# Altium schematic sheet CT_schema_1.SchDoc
size 678 x 615 mm
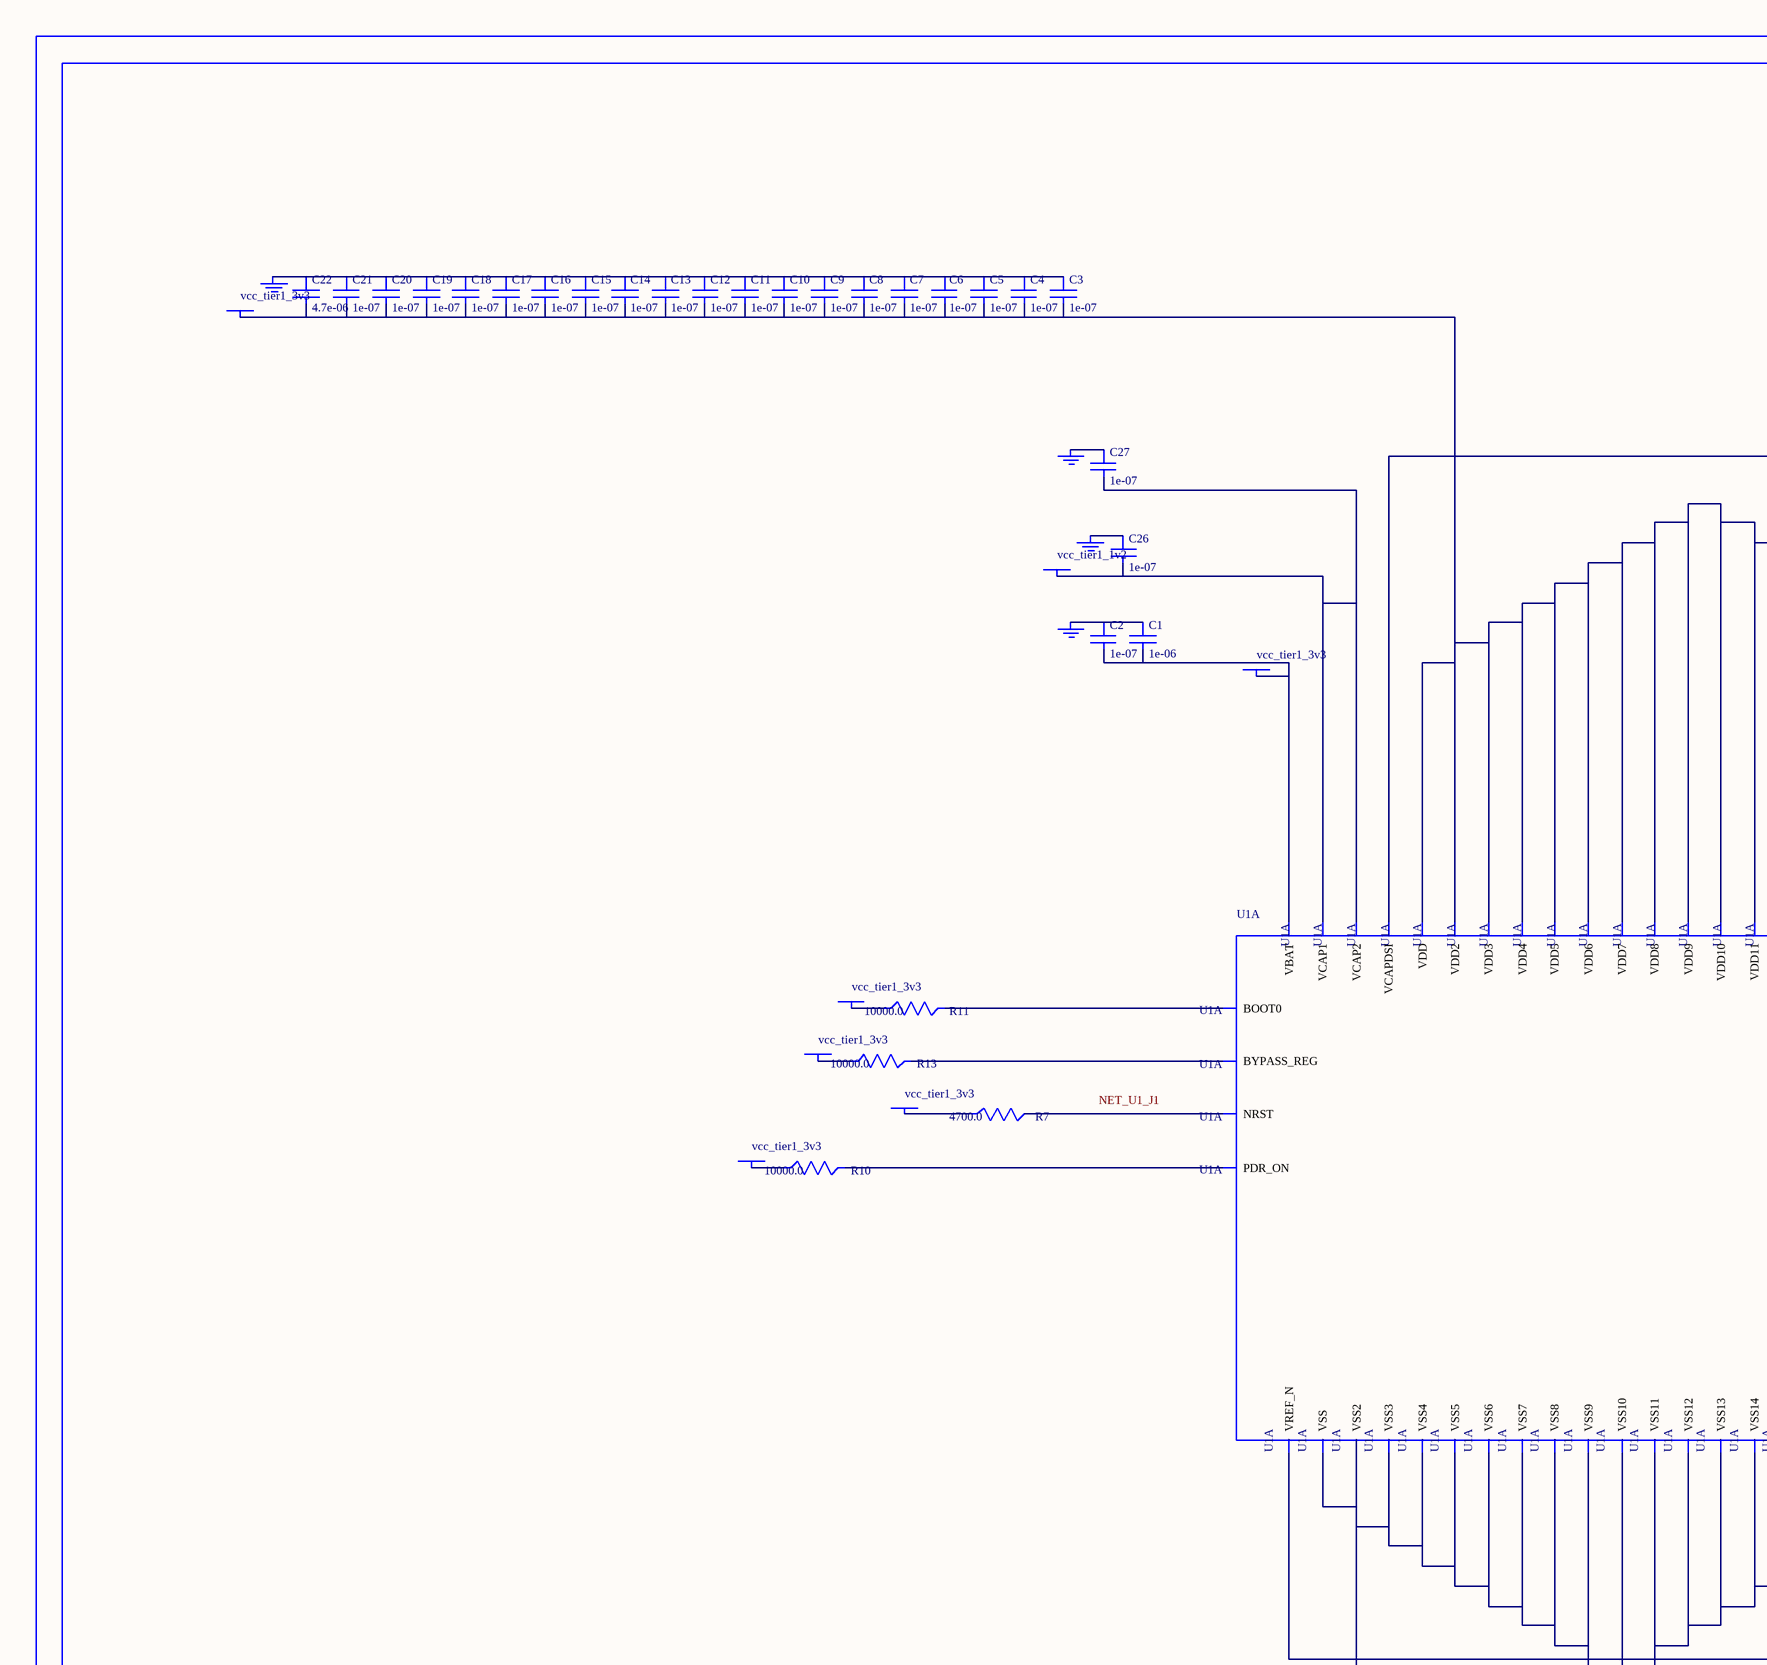
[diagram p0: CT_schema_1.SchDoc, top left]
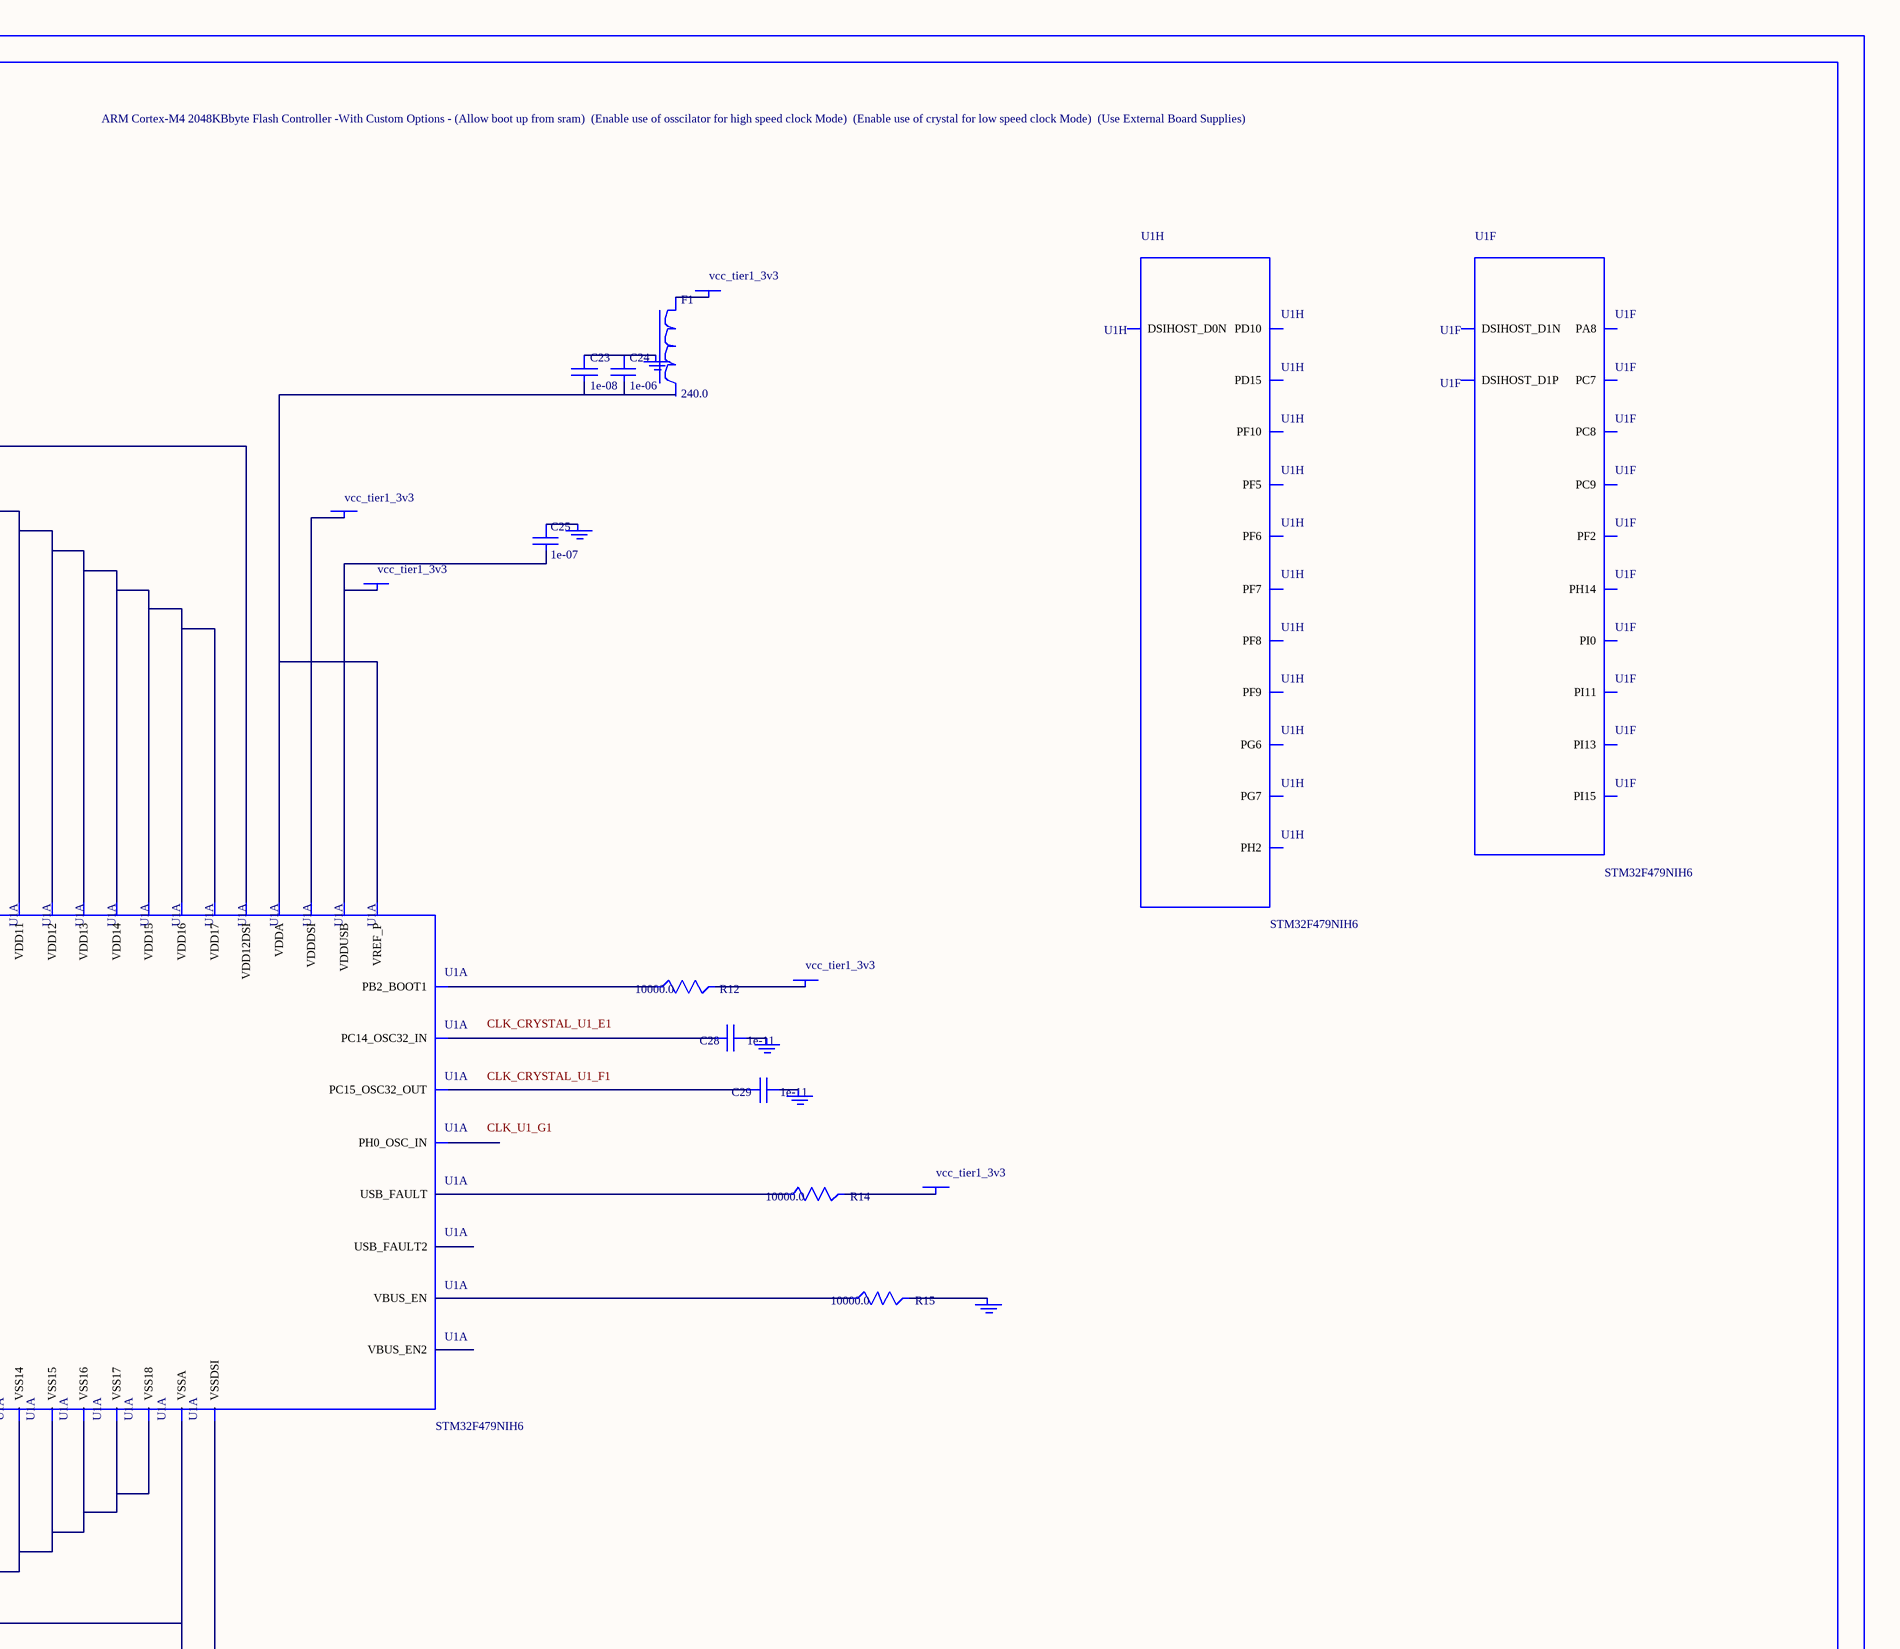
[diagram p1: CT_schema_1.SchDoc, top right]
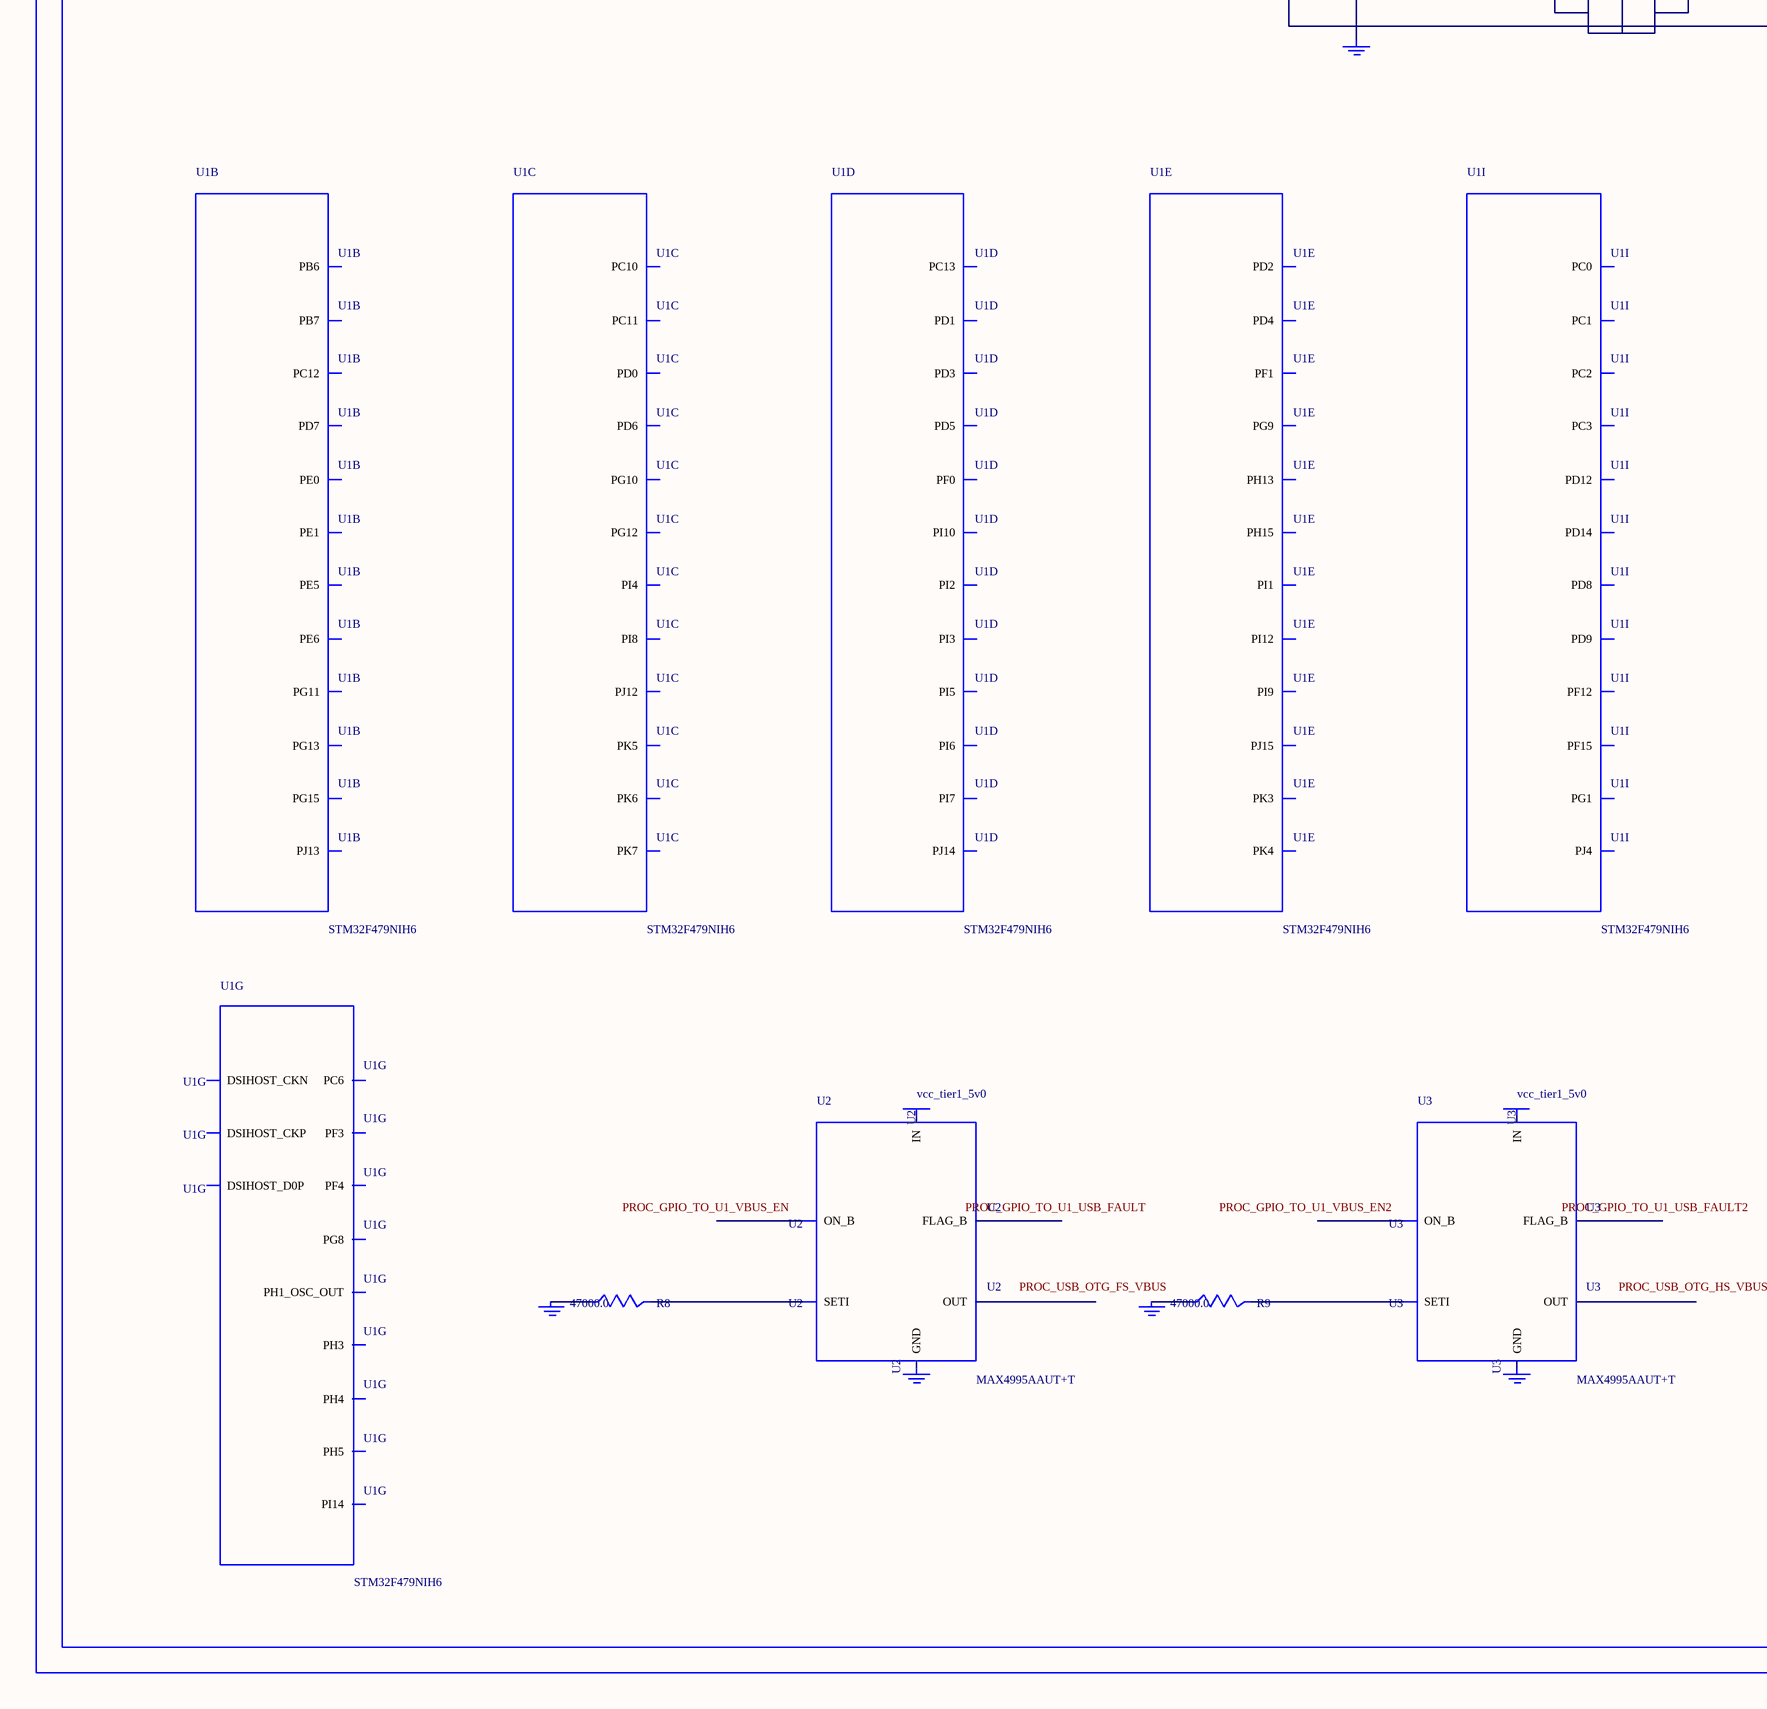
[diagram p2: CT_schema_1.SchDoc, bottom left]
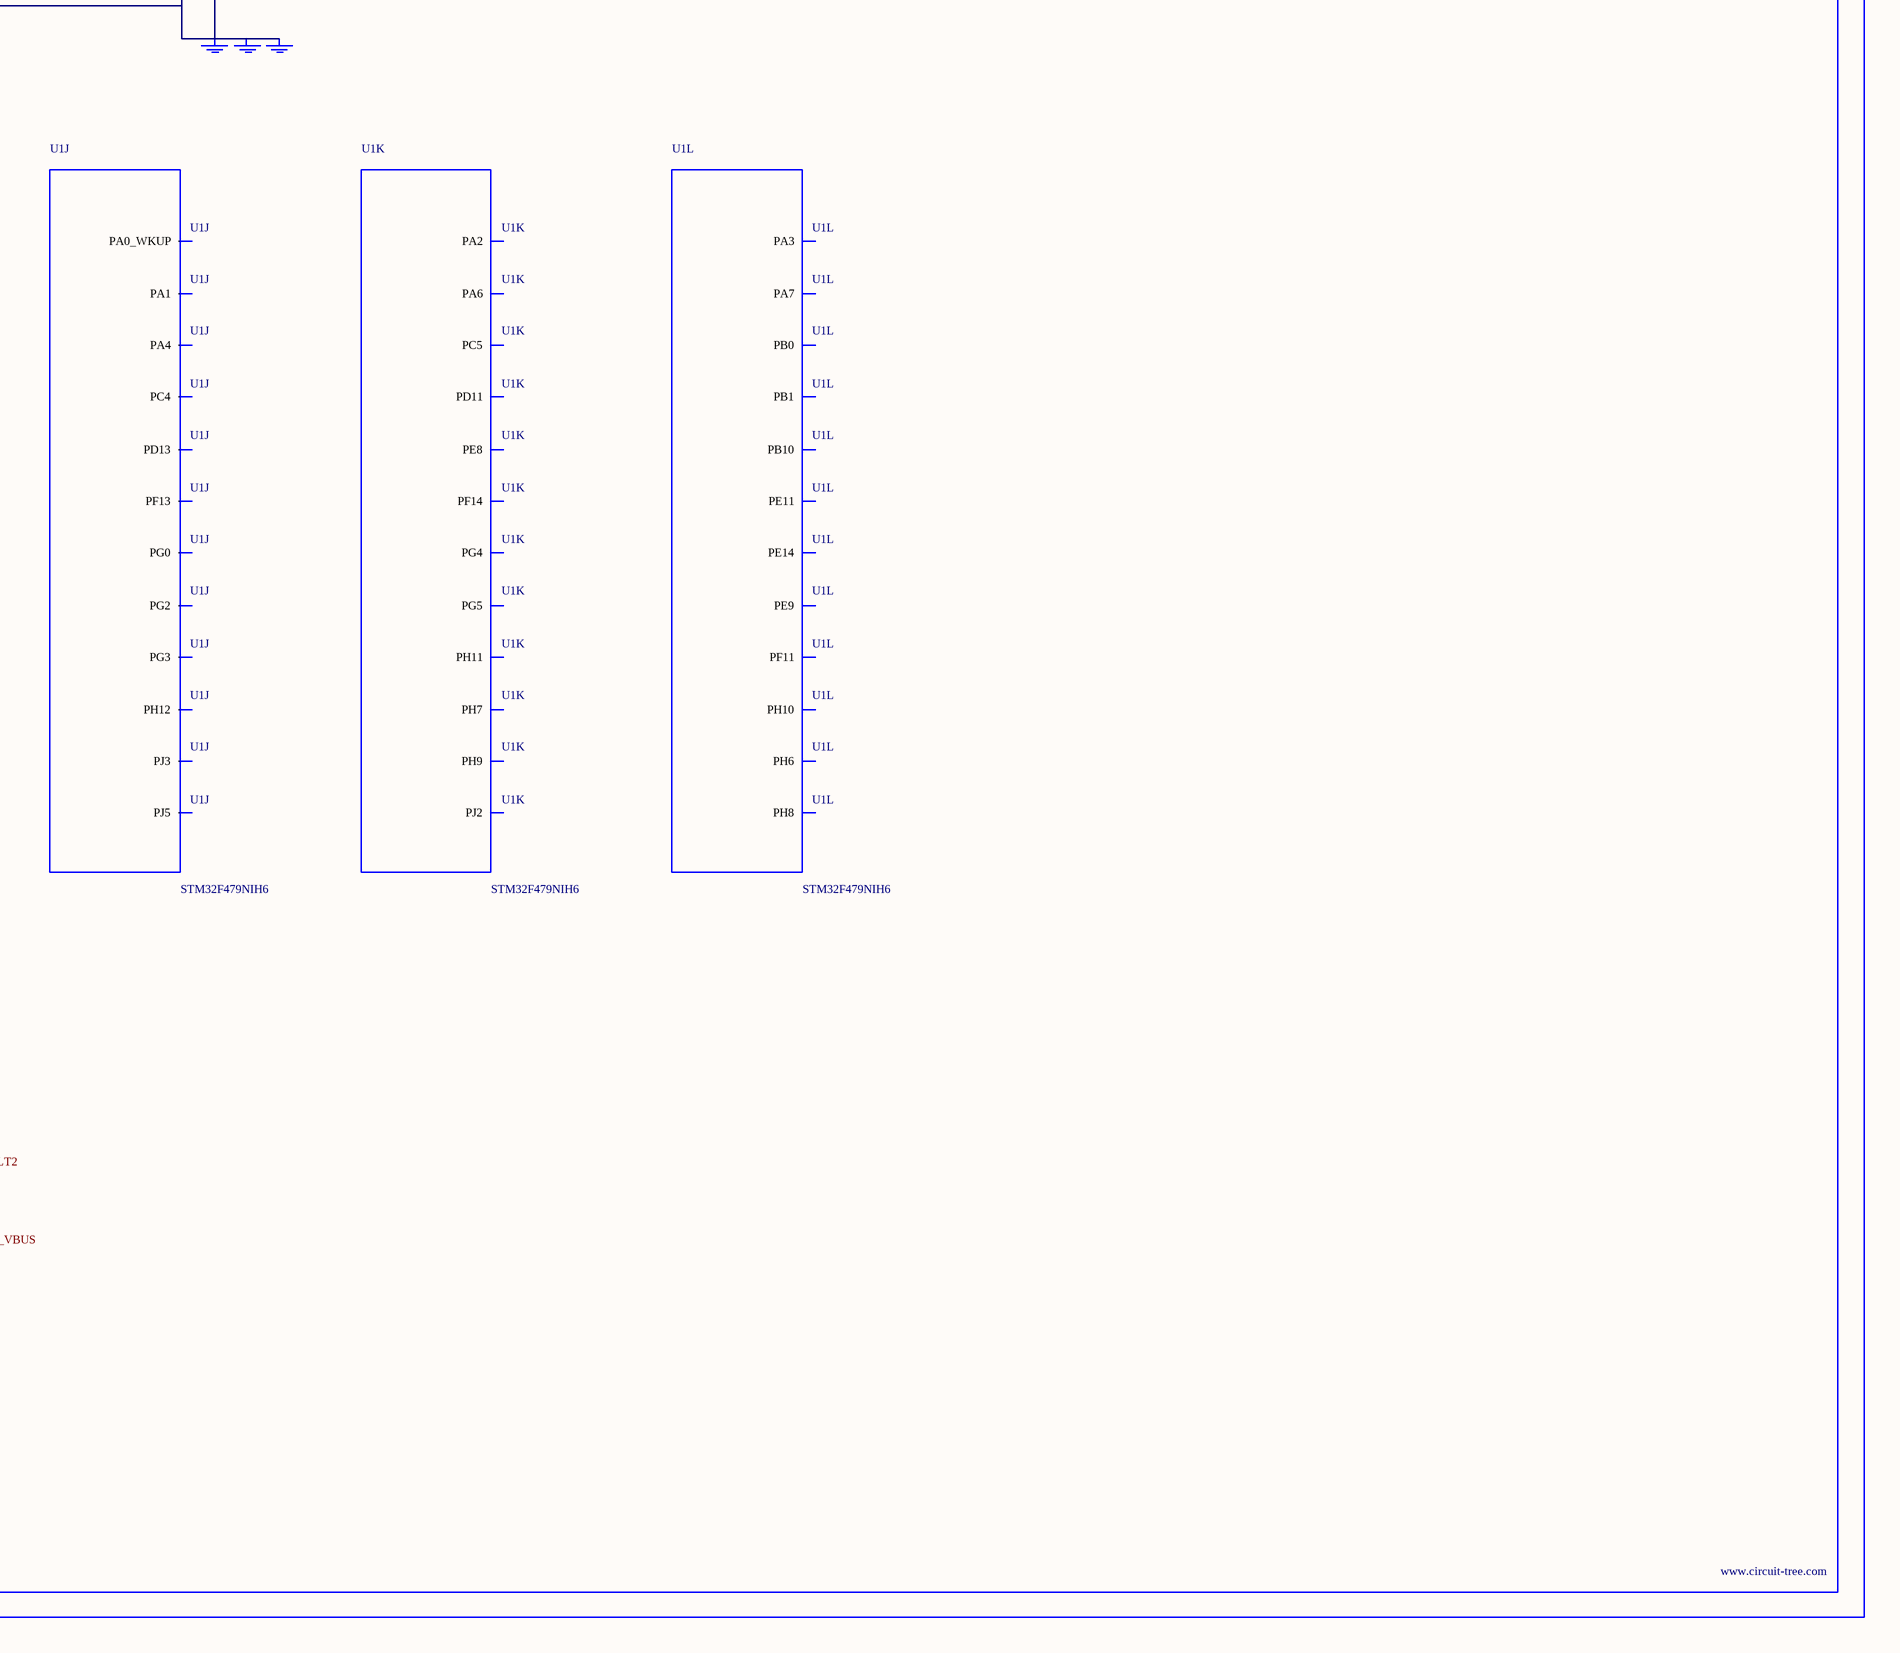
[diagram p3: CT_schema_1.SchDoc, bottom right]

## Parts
BORDER0  (no value)
C1  1e-06  [C0603]
C2  1e-07  [C0603]
C3  1e-07  [C0603]
C4  1e-07  [C0603]
C5  1e-07  [C0603]
C6  1e-07  [C0603]
C7  1e-07  [C0603]
C8  1e-07  [C0603]
C9  1e-07  [C0603]
C10  1e-07  [C0603]
C11  1e-07  [C0603]
C12  1e-07  [C0603]
C13  1e-07  [C0603]
C14  1e-07  [C0603]
C15  1e-07  [C0603]
C16  1e-07  [C0603]
C17  1e-07  [C0603]
C18  1e-07  [C0603]
C19  1e-07  [C0603]
C20  1e-07  [C0603]
C21  1e-07  [C0603]
C22  4.7e-06  [C0603]
C23  1e-08  [C0603]
C24  1e-06  [C0603]
C25  1e-07  [C0603]
C26  1e-07  [C0603]
C27  1e-07  [C0603]
C28  1e-11  [C0402]
C29  1e-11  [C0402]
F1  240.0  [L0603]
GND_INSTANCE_0_0  (no value)
GND_INSTANCE_0_1  (no value)
GND_INSTANCE_0_2  (no value)
GND_INSTANCE_0_3  (no value)
GND_INSTANCE_0_4  (no value)
GND_INSTANCE_0_5  (no value)
GND_INSTANCE_0_6  (no value)
GND_INSTANCE_0_7  (no value)
GND_INSTANCE_0_8  (no value)
GND_INSTANCE_0_9  (no value)
GND_INSTANCE_0_10  (no value)
GND_INSTANCE_0_11  (no value)
GND_INSTANCE_0_12  (no value)
GND_INSTANCE_0_13  (no value)
GND_INSTANCE_0_14  (no value)
GND_INSTANCE_0_15  (no value)
GND_INSTANCE_0_16  (no value)
POWER_INSTANCE_0_0  vcc_tier1_3v3
POWER_INSTANCE_0_1  vcc_tier1_3v3
POWER_INSTANCE_0_2  vcc_tier1_3v3
POWER_INSTANCE_0_3  vcc_tier1_3v3
POWER_INSTANCE_0_4  vcc_tier1_3v3
POWER_INSTANCE_0_5  vcc_tier1_3v3
POWER_INSTANCE_0_6  vcc_tier1_3v3
POWER_INSTANCE_0_7  vcc_tier1_3v3
POWER_INSTANCE_0_8  vcc_tier1_1v2
POWER_INSTANCE_0_9  vcc_tier1_3v3
POWER_INSTANCE_0_10  vcc_tier1_3v3
POWER_INSTANCE_0_11  vcc_tier1_3v3
POWER_INSTANCE_0_12  vcc_tier1_5v0
POWER_INSTANCE_0_13  vcc_tier1_5v0
R7  4700.0  [R0603]
R8  47000.0  [R0603]
R9  47000.0  [R0603]
R10  10000.0  [R0603]
R11  10000.0  [R0603]
R12  10000.0  [R0603]
R13  10000.0  [R0603]
R14  10000.0  [R0603]
R15  10000.0  [R0603]
U1  STM32F479NIH6  [TFBGA216]  (parts A,B,C,D,E,F,G,H,I,J,K,L of 17)
U2  MAX4995AAUT+T  [SOT-23-6]
U3  MAX4995AAUT+T  [SOT-23-6]

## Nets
NetC1_1: C1.1 C2.1 GND_INSTANCE_0_0.0(GND)
NetC1_2: C1.2 C2.2 POWER_INSTANCE_0_0.0(PWR) U1.C1(VBAT)
NetC3_1: C3.1 C4.1 C5.1 C6.1 C7.1 C8.1 C9.1 C10.1 C11.1 C12.1 C13.1 C14.1 C15.1 C16.1 C17.1 C18.1 C19.1 C20.1 C21.1 C22.1 GND_INSTANCE_0_2.0(GND)
NetC3_2: C3.2 C4.2 C5.2 C6.2 C7.2 C8.2 C9.2 C10.2 C11.2 C12.2 C13.2 C14.2 C15.2 C16.2 C17.2 C18.2 C19.2 C20.2 C21.2 C22.2 POWER_INSTANCE_0_2.0(PWR) U1.E7(VDD2) U1.E8(VDD3) U1.E9(VDD4) U1.E10(VDD) U1.F4(VDD6) U1.F5(VDD7) U1.F11(VDD5) U1.G5(VDD8) U1.H5(VDD9) U1.J5(VDD11) U1.J11(VDD10) U1.K5(VDD13) U1.K11(VDD12) U1.L7(VDD15) U1.L8(VDD16) U1.L9(VDD17) U1.L10(VDD14)
NetC23_1: C23.1 C24.1 GND_INSTANCE_0_1.0(GND)
NetC23_2: C23.2 C24.2 U1.P1(VREF_P) U1.R1(VDDA)
NetC25_1: C25.1 GND_INSTANCE_0_3.0(GND)
NetC25_2: C25.2 POWER_INSTANCE_0_4.0(PWR) U1.G11(VDDUSB)
NetC26_1: C26.1 GND_INSTANCE_0_4.0(GND)
NetC26_2: C26.2 C27.2 POWER_INSTANCE_0_8.0(PWR) U1.E11(VCAP2) U1.L11(VCAP1)
NetC27_1: C27.1 GND_INSTANCE_0_5.0(GND)
NetC28_1: C28.1 GND_INSTANCE_0_6.0(GND)
NetC28_2: C28.2 U1.E1(PC14_OSC32_IN)
NetC29_1: C29.1 GND_INSTANCE_0_7.0(GND)
NetC29_2: C29.2 U1.F1(PC15_OSC32_OUT)
NetF1_1: F1.1 POWER_INSTANCE_0_1.0(PWR)
NetGND_INSTANCE_0_8_0: GND_INSTANCE_0_8.0(GND) R15.2
NetGND_INSTANCE_0_9_0: GND_INSTANCE_0_9.0(GND) GND_INSTANCE_0_10.0(GND) GND_INSTANCE_0_11.0(GND) U1.G12(VSSDSI) U1.M1(VSSA) U1.N1(VREF_N)
NetGND_INSTANCE_0_12_0: GND_INSTANCE_0_12.0(GND) U1.F2(VSS2) U1.F6(VSS3) U1.F7(VSS4) U1.F8(VSS5) U1.F9(VSS6) U1.F10(VSS) U1.G6(VSS8) U1.G10(VSS7) U1.H6(VSS10) U1.H10(VSS9) U1.J6(VSS12) U1.J10(VSS11) U1.K6(VSS14) U1.K7(VSS15) U1.K8(VSS16) U1.K9(VSS17) U1.K10(VSS13) U1.L6(VSS18)
NetGND_INSTANCE_0_13_0: GND_INSTANCE_0_13.0(GND) R8.1
NetGND_INSTANCE_0_15_0: GND_INSTANCE_0_15.0(GND) R9.1
NetPOWER_INSTANCE_0_3_0: POWER_INSTANCE_0_3.0(PWR) R10.1
NetPOWER_INSTANCE_0_5_0: POWER_INSTANCE_0_5.0(PWR) R11.1
NetPOWER_INSTANCE_0_6_0: POWER_INSTANCE_0_6.0(PWR) R12.2
NetPOWER_INSTANCE_0_7_0: POWER_INSTANCE_0_7.0(PWR) R13.1
NetPOWER_INSTANCE_0_9_0: POWER_INSTANCE_0_9.0(PWR) R14.2
NetPOWER_INSTANCE_0_10_0: POWER_INSTANCE_0_10.0(PWR) U1.H11(VDDDSI)
NetPOWER_INSTANCE_0_11_0: POWER_INSTANCE_0_11.0(PWR) R7.1
NetR7_2: R7.2 U1.J1(NRST)
NetR8_2: R8.2 U2.3(SETI)
NetR9_2: R9.2 U3.3(SETI)
NetR10_2: R10.2 U1.E5(PDR_ON)
NetR11_2: R11.2 U1.E6(BOOT0)
NetR12_1: R12.1 U1.M5(PB2_BOOT1)
NetR13_2: R13.2 U1.L5(BYPASS_REG)
NetR14_1: R14.1 U1.A2(USB_FAULT)
NetR15_1: R15.1 U1.A1(VBUS_EN)
NetU1_G13: U1.G13(VDD12DSI) U1.K12(VCAPDSI)

Not connected (* = marked no-connect by the designer): F1 2; GND_INSTANCE_0_14 0(GND); GND_INSTANCE_0_16 0(GND); POWER_INSTANCE_0_12 0(PWR); POWER_INSTANCE_0_13 0(PWR); U1 A3(VBUS_EN2) A4(USB_FAULT2) A5(PE1) A6(PE0) A11(PD7) A12(PC12) B1(PE5) B2(PE6) B3(PG13) B5(PB7) B6(PB6) B7(PG15) B8(PG11) B9(PJ13) B10(PJ12) B11(PD6) B12(PD0) B13(PC11) B14(PC10) C2(PI8) C3(PI4) C4(PK7) C5(PK6) C6(PK5) C7(PG12) C8(PG10) C9(PJ14) C10(PD5) C11(PD3) C12(PD1) C13(PI3) C14(PI2) D1(PC13) D2(PF0) D3(PI5) D4(PI7) D5(PI10) D6(PI6) D7(PK4) D8(PK3) D9(PG9) D10(PJ15) D11(PD4) D12(PD2) D13(PH15) D14(PI1) E2(PF1) E3(PI12) E4(PI9) E12(PH13) E13(PH14) E14(PI0) F3(PI11) F12(DSIHOST_D1P) F13(DSIHOST_D1N) F14(PC9) F15(PA8) G1(PH0_OSC_IN) G2(PF2) G3(PI13) G4(PI15) G14(PC8) G15(PC7) H1(PH1_OSC_OUT) H2(PF3) H3(PI14) H4(PH4) H12(DSIHOST_CKP) H13(DSIHOST_CKN) H14(PG8) H15(PC6) J2(PF4) J3(PH5) J4(PH3) J12(DSIHOST_D0P) J13(DSIHOST_D0N) J14(PG7) J15(PG6) K1(PF7) K2(PF6) K3(PF5) K4(PH2) K13(PD15) K15(PD10) L1(PF10) L2(PF9) L3(PF8) L4(PC3) L12(PD14) L14(PD9) L15(PD8) M2(PC0) M3(PC1) M4(PC2) M6(PF12) M7(PG1) M8(PF15) M9(PJ4) M10(PD12) M11(PD13) M12(PG3) M13(PG2) M14(PJ5) M15(PH12) N2(PA1) N3(PA0_WKUP) N4(PA4) N5(PC4) N6(PF13) N7(PG0) N8(PJ3) N9(PE8) N10(PD11) N11(PG5) N12(PG4) N13(PH7) N14(PH9) N15(PH11) P2(PA2) P3(PA6) P5(PC5) P6(PF14) P7(PJ2) P8(PF11) P9(PE9) P10(PE11) P11(PE14) P12(PB10) P13(PH6) P14(PH8) P15(PH10) R2(PA3) R3(PA7) R4(PB1) R5(PB0); U2 1(OUT) 2(GND) 4(ON_B) 5(IN) 6(FLAG_B); U3 1(OUT) 2(GND) 4(ON_B) 5(IN) 6(FLAG_B)

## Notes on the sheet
- Labels drawn without touching a wire or pin: CLK_CRYSTAL_U1_E1, CLK_CRYSTAL_U1_F1, CLK_U1_G1, NET_U1_J1, PROC_GPIO_TO_U1_USB_FAULT, PROC_GPIO_TO_U1_USB_FAULT2, PROC_GPIO_TO_U1_VBUS_EN, PROC_GPIO_TO_U1_VBUS_EN2, PROC_USB_OTG_FS_VBUS, PROC_USB_OTG_HS_VBUS

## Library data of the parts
BORDER0 = BORDER_PAGE0
C1 C24 = C0603C105K3RACTU
C2-C21 C25-C27 = 06035C104K4Z2A
C22 = GRM188R6YA475KE15D
C23 = 06035C103K4Z2A
C28 C29 = C0402C100K3GACTU
F1 = Z0603C241ASMST
GND_INSTANCE_0_0-GND_INSTANCE_0_16 = GND
POWER_INSTANCE_0_0-POWER_INSTANCE_0_13 = PWR
R7 = RC0603JR-074K7L
R8 R9 = RC0603JR-0747KL
R10-R15 = RC0603JR-0710KL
